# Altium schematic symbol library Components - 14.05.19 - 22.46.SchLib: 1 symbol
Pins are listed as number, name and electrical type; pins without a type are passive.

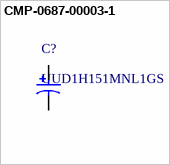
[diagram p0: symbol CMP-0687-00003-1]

## CMP-0687-00003-1
designator C?, comment UUD1H151MNL1GS
Aluminum Electrolytic Capacitor, UD Series, Low Impedance, 150 uF, 50 V, + / - 20%, -55 to 105 degC, Chip Type, 10 x 10 mm D x L, Pb-Free, Reel; Manufacturer: Nichicon; Rated Ripple Current (at 100kHz): 670 mA; Impedance: 0.18 Ohm; Packing: Dia382mm Reel; Rated Capacitance: 150 uF; Tolerance Rated Capacitance: -20 to 20%; Rated Voltage: 50 V; Endurance Time: 5000 h
footprint NIC-CAPA2-10X10_V (Aluminum Electrolytic Capacitor, Diameter 10mm, Height 10.8mm, Pitch 8mm)
pins: 1, 2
